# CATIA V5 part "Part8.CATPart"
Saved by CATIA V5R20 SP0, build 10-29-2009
Part number: 9FP1205M4
Revision: ANY
Definition: UNKNOWN
Nomenclature: 9FP1205M4
Source: Unknown
Bounding box of the stored display mesh (mm): x -5.752 to 5.752, y 0 to 5, z -5.9 to 5.9
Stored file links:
  C:\Users\Utente\Desktop\IO LAVORO\3D X SITO CF\CUMSA\3D files PW\pw060622\pw060622_injection\Part8.CATPart
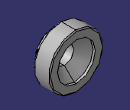
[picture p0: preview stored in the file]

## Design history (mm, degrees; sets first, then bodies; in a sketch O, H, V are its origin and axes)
Body1 "Redondeo2" (main body)
  Solid1: solid without history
